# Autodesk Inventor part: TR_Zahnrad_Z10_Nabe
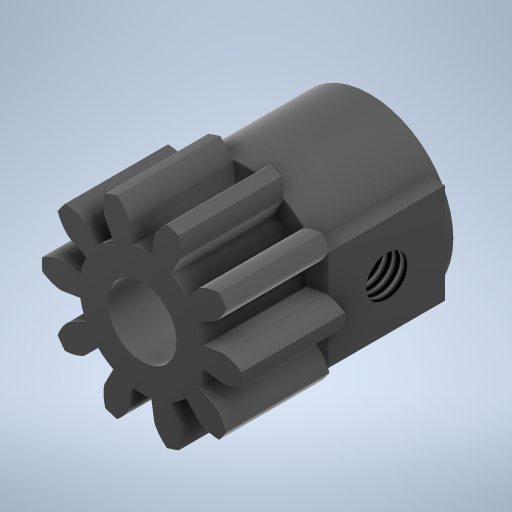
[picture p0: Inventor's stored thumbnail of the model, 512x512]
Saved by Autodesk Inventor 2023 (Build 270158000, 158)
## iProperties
Created: 2023-11
Part Number: TR_Zahnrad_Z10_Nabe
Material: PBT-Kunststoff
Document SubType Name: Modeling
Designer: AdminForWorker
Density: 1.31 g/cm^3
Appearance: Glatt - Schwarz
Title: Component1
Author: AdminForWorker
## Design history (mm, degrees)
feature "Body1"
sketch "Skizze1"
  geometry: C1 r 5 at (0, 0); 1 further point
  constraints: 1 centre point, 1 coincident
  dimensions: "d0" = 10 diameter of C1 (= Einheitsmaß)
extrude "Extrusion1" join sketch "Skizze1" distance "d1" = 7.5; taper "d2" = 0 deg
sketch "Skizze2"
  geometry: L1 (3, 0)-(-3, 0); L2 (-3, 0)-(-3, -7); L3 (-3, -7)-(3, -7); L4 (3, -7)-(3, 0); L5 (0.374, 0)-(-0.374, 0) reference; 2 further points
  constraints: 8 end point, 2 midpoint, 2 parallel, 1 horizontal, 1 perpendicular
  dimensions: "d3" = 7 distance of L3.end L1.start; "d4" = 6 distance of L2.end L3.end
extrude "Extrusion2" join sketch "Skizze2" distance "d5" = 5 (= 0.5 x Einheitsmaß); taper "d6" = 0 deg
sketch "Skizze3"
  geometry: L1 (7, 3)-(0, 3) reference; L2 (0, 0.374)-(0, -0.374) reference; 4 further points
  constraints: 2 midpoint, 1 horizontal alignment, 1 vertical alignment
hole "Bohrung1" sketch "Skizze3" at (3.5, 0) diameter "d7" = 2.459; stored, may be unused: countersink angle "d11" = 90 deg, drill point angle "d13" = 0 deg; dims "d8" = 5, "d9" = 4, "d10" = 2, "d12" = 5
sketch "Skizze4"
  geometry: C1 r 2.075 at (0, 0); 1 further point
  constraints: 1 centre point, 1 coincident
  dimensions: "d14" = 4.15 diameter of C1 (= 2 x Radius)
extrude "Extrusion3" cut sketch "Skizze4" extent not by distance; stored distance "d15" = 0; taper "d16" = 0 deg
body "Solid1"
other parameters: "Einheitsmaß" = 10 [user parameter; used in 2 equation terms], "Radius" = 2.075 [user parameter; used in 1 equation term], "Fasen" = 0.5 [user parameter], "Dicke" = 0.8 [user parameter], "Breitloch" = 2 [user parameter], "Langloch" = 32 [user parameter], "AchteckUmkreis" = 6 [user parameter], "DAchsAufnahme" = 4.1 [user parameter], "AchsDurchmesser" = 4 [user parameter], "AchsFase" = 0.5 [user parameter]
